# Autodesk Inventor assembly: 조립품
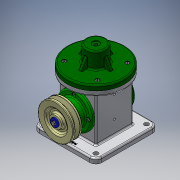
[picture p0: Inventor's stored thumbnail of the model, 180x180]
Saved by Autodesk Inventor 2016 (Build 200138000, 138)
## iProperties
Created: 2021-05
Part Number: 조립품
Material: 일반
Document SubType Name: Assembly
Designer: Windows7
Author: Windows7
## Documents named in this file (19)
- C:\Users\Windows7\Desktop\710506V1004\조립품.iam
- C:\Users\Windows7\Desktop\710506V1004\본체.ipt
- C:\Users\Windows7\Desktop\710506V1004\편심축.ipt
- C:\Users\Windows7\Desktop\710506V1004\앞커버.ipt
- C:\Users\Windows7\Desktop\710506V1004\베어링 17 x 40 x 12.ipt
- C:\Users\Windows7\Desktop\710506V1004\V-벨트풀리.ipt
- C:\Users\Windows7\Desktop\710506V1004\오일 실 17 30 8.ipt
- C:\Users\Windows7\Desktop\710506V1004\키 4 x 4 x 12.ipt
- C:\Users\Windows7\Desktop\710506V1004\뒤커버.ipt
- C:\Users\Windows7\Desktop\710506V1004\E-링.ipt
- C:\Users\Windows7\Desktop\710506V1004\와셔 4x16.ipt
- C:\Users\Windows7\Desktop\710506V1004\볼트 M4 x 10.ipt
- C:\Users\Windows7\Desktop\710506V1004\볼트 M4 x 12.ipt
- 볼트 M4 x 12.ipt
- C:\Users\Windows7\Desktop\710506V1004\덮개.ipt
- C:\Users\Windows7\Desktop\710506V1004\링크.ipt
- C:\Users\Windows7\Desktop\710506V1004\슬라이더.ipt
- C:\Users\Windows7\Desktop\710506V1004\클레비스 핀 6 x 22.ipt
- 클레비스 핀 6 x 22.ipt
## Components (2 placed, 2 different names)
1. V-벨트풀리:1
2. E-링:1
